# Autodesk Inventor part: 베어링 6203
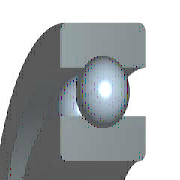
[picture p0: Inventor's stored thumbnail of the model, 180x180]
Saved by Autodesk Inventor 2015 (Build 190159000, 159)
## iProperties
IsCustomPart: 0
Created: 2016-05
Part Number: 베어링 6203
Material: 강철, 연강
Description: 깊은 그루브 볼 베어링
Document SubType Name: Modeling
Standard: KS B 2023
Designer: mduedu
Standards Organization: KS
Language: ko-KR
Size Designation: 6203 - 17 x 40 x 12
Categories: <MemberInstance><Categories><Category DisplayName="샤프트 부품" InternalName="7f7aeb1f-a693-4053-b835-cee3144e0d98" Mnemonic="SHFT"><Category DisplayName="베어링" Inter
Density: 1 g/cm^3
Appearance: 노란색
Author: mduedu
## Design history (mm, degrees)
sketch "스케치" dims "d0" = 5.98 (= -0.26 x WD + 0.26 x BD)
  geometry: L1 (3.01, 14.25)-(8.99, 14.25); L2 (6, 14.25)-(6, 11.26); L3 (6, 14.25)-(6, 17.24); L4 (3.778, 12.249)-(0, 12.249); L5 (0, 8.5)-(12, 8.5); L6 (3.778, 16.251)-(0, 16.251); L7 (0, 20)-(12, 20); L8 (12, 8.5)-(12, 12.249); L9 (8.222, 12.249)-(12, 12.249); L10 (8.222, 16.251)-(12, 16.251); L11 (12, 20)-(12, 16.251); L12 (-1.4, 0)-(8.4, 0) reference; L13 (0, -0.3)-(0, 5.3) reference
  constraints: 22 end point, 4 point on line, 2 collinear, 2 perpendicular, 2 symmetric about line, 1 midpoint, 1 parallel, 14 other
  dimensions: "d9" = 17 diameter of L5 L12 (= WD); "d11" = 40 diameter of L7 L12 (= BD); "d12" = 12 distance between parallel lines of L8 L13 (= KB); "d13" = 24.498 diameter of L9 L12 (= 0.326 x BD + 0.674 x WD)
revolve "본체" stored, may be unused: angle "d6" = 90 deg
revolve "볼" stored, may be unused: angle "d7" = 90 deg
pattern_circular "IDS_ARRAYBALL[SIMPL:T]" dims angle "d3" = 360 deg
body "Solid1"
fillet "모깎기1" dims "d1" = 0.6 (= KRS)
other parameters: "WD" = 17 [user parameter; used in 5 equation terms], "BD" = 40 [user parameter; used in 5 equation terms], "KB" = 12 [user parameter; used in 1 equation term], "KRS" = 0.6 [user parameter; used in 1 equation term], "d4" = 0, "d5" = 0, "d8" = 0, "d14" = 0, "d15" = 0, "BBA" = 0 [user parameter], "BC0" = 4750000 [user parameter], "BC" = 9560000 [user parameter], "WR" = 8.5 (= 0.5 x WD) [user parameter]
